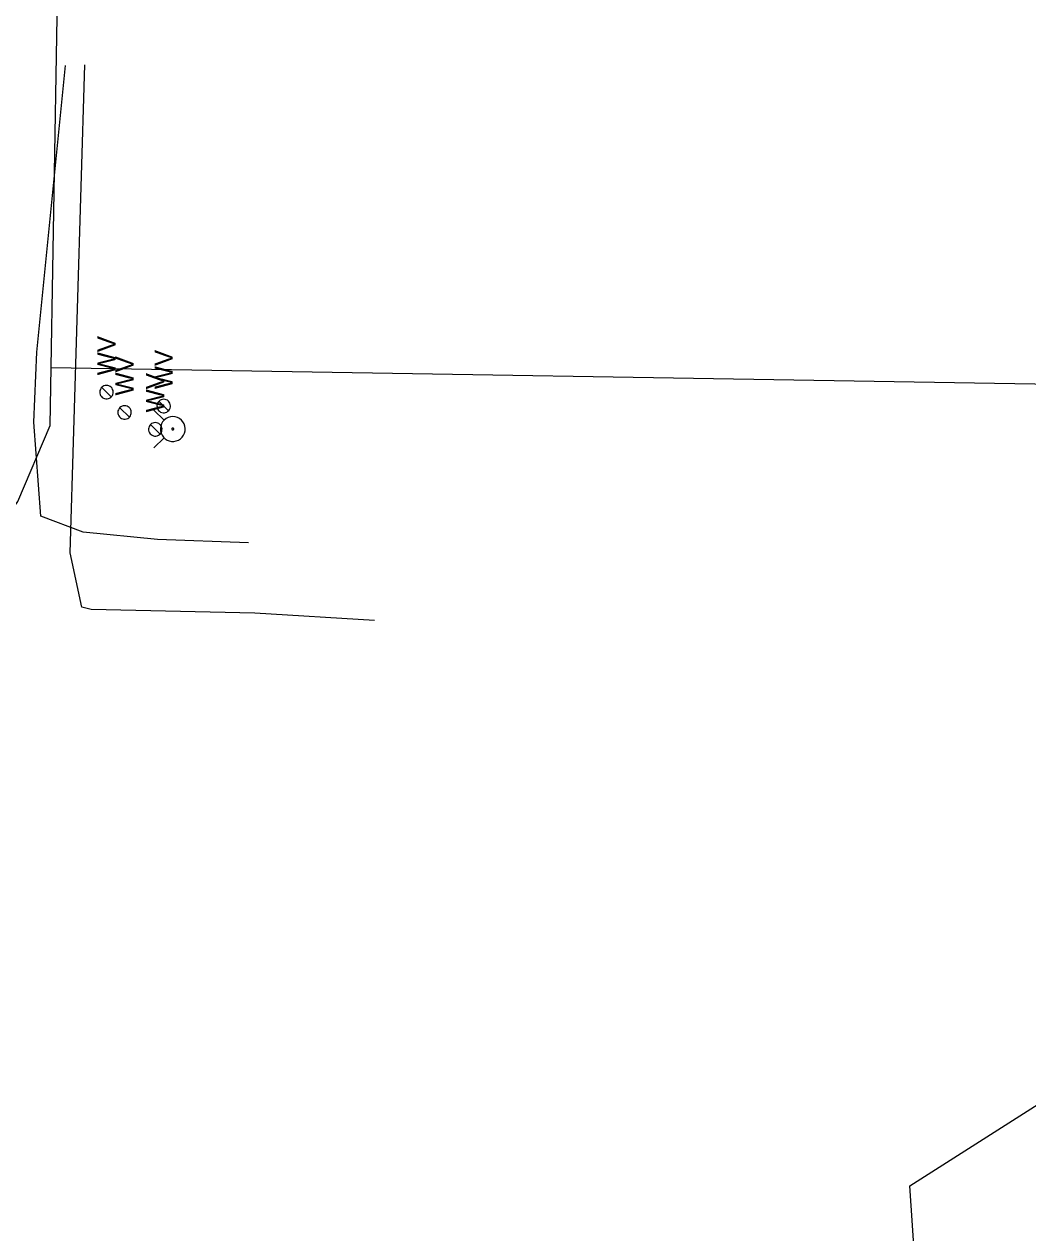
# Model space of a CAD drawing. Extents: x 596028 to 606371, y 330010 to 403088.
# Drawn here: x 604631.6 to 604843.1, y 338176.7 to 338431.5 of the extents above; entities that cross this region are included whole.
import ezdxf

# ---------------------------------------------------------------- set-up
doc = ezdxf.new("R2010")
doc.units = 0
for name, color, linetype in [('E_UTL_E_UG', 7, 'Continuous'), ('E_UTL_G_UG', 7, 'Continuous'), ('E_UTL_W', 7, 'Continuous'), ('E_UTL_WHydrant', 7, 'Continuous')]:
    doc.layers.add(name, color=color, linetype=linetype)

msp = doc.modelspace()

# ---------------------------------------------------------------- linework, layer by layer
at = {"layer": 'E_UTL_E_UG'}
for p, q in [((604637.05, 338346.84), (604638.82, 338452.87)), ((604637.25, 338359.09), (604911.55, 338354.56))]:
    msp.add_line(p, q, dxfattribs=at)
for points in [[(604678.85, 338322.09), (604659.64, 338322.8), (604643.99, 338324.36), (604635.04, 338327.77), (604633.62, 338347.59), (604634.2, 338362.29), (604640.26, 338422.74)], [(604617.83, 338316.39), (604626.08, 338325.01), (604630.22, 338330.84), (604637.05, 338346.84)], [(604825.46, 338093.49), (604823.34, 338111.37), (604818.25, 338186.57), (604849.14, 338206.21), (604870.72, 338198.67)]]:
    msp.add_lwpolyline(points, dxfattribs=at)
at = {"layer": 'E_UTL_G_UG'}
msp.add_lwpolyline([(604705.4, 338305.74), (604680.17, 338307.27), (604645.65, 338308.04), (604643.7, 338308.56), (604641.22, 338319.99), (604644.37, 338422.86)], dxfattribs=at)
at = {"layer": 'E_UTL_W'}
for points in [[(604648.9, 338355.3), (604648.63, 338355.28), (604648.37, 338355.2), (604648.13, 338355.08), (604647.92, 338354.91), (604647.74, 338354.7), (604647.61, 338354.47), (604647.52, 338354.21), (604647.48, 338353.95), (604647.49, 338353.67), (604647.56, 338353.41), (604647.67, 338353.16), (604647.83, 338352.94), (604648.02, 338352.76), (604648.25, 338352.61), (604648.5, 338352.51), (604648.77, 338352.46), (604649.04, 338352.46), (604649.31, 338352.51), (604649.56, 338352.61), (604649.79, 338352.76), (604649.98, 338352.94), (604650.14, 338353.16), (604650.25, 338353.41), (604650.31, 338353.67), (604650.33, 338353.95), (604650.29, 338354.21), (604650.2, 338354.47), (604650.07, 338354.7), (604649.89, 338354.91), (604649.67, 338355.08), (604649.43, 338355.2), (604649.17, 338355.28), (604648.9, 338355.3)], [(604649.91, 338352.87), (604647.9, 338354.89)], [(604652.72, 338351.03), (604652.45, 338351), (604652.19, 338350.93), (604651.95, 338350.8), (604651.74, 338350.63), (604651.56, 338350.43), (604651.42, 338350.19), (604651.33, 338349.94), (604651.3, 338349.67), (604651.31, 338349.4), (604651.37, 338349.14), (604651.49, 338348.89), (604651.64, 338348.67), (604651.84, 338348.48), (604652.07, 338348.33), (604652.32, 338348.23), (604652.59, 338348.18), (604652.86, 338348.18), (604653.12, 338348.23), (604653.37, 338348.33), (604653.6, 338348.48), (604653.8, 338348.67), (604653.96, 338348.89), (604654.07, 338349.14), (604654.13, 338349.4), (604654.14, 338349.67), (604654.11, 338349.94), (604654.02, 338350.19), (604653.88, 338350.43), (604653.7, 338350.63), (604653.49, 338350.8), (604653.25, 338350.93), (604652.99, 338351), (604652.72, 338351.03)], [(604653.73, 338348.59), (604651.71, 338350.61)], [(604660.97, 338352.38), (604660.7, 338352.36), (604660.44, 338352.28), (604660.2, 338352.16), (604659.98, 338351.99), (604659.81, 338351.79), (604659.67, 338351.55), (604659.58, 338351.29), (604659.54, 338351.03), (604659.56, 338350.76), (604659.62, 338350.49), (604659.73, 338350.25), (604659.89, 338350.02), (604660.09, 338349.84), (604660.31, 338349.69), (604660.57, 338349.59), (604660.83, 338349.54), (604661.1, 338349.54), (604661.37, 338349.59), (604661.62, 338349.69), (604661.85, 338349.84), (604662.05, 338350.02), (604662.2, 338350.25), (604662.32, 338350.49), (604662.38, 338350.76), (604662.39, 338351.03), (604662.35, 338351.29), (604662.26, 338351.55), (604662.13, 338351.79), (604661.95, 338351.99), (604661.74, 338352.16), (604661.5, 338352.28), (604661.24, 338352.36), (604660.97, 338352.38)], [(604661.98, 338349.95), (604659.96, 338351.97)], [(604659.19, 338347.48), (604658.92, 338347.45), (604658.66, 338347.38), (604658.42, 338347.25), (604658.2, 338347.09), (604658.03, 338346.88), (604657.89, 338346.65), (604657.8, 338346.39), (604657.76, 338346.12), (604657.78, 338345.85), (604657.84, 338345.59), (604657.95, 338345.34), (604658.11, 338345.12), (604658.31, 338344.93), (604658.53, 338344.79), (604658.79, 338344.69), (604659.05, 338344.63), (604659.32, 338344.63), (604659.59, 338344.69), (604659.84, 338344.79), (604660.07, 338344.93), (604660.27, 338345.12), (604660.42, 338345.34), (604660.54, 338345.59), (604660.6, 338345.85), (604660.61, 338346.12), (604660.57, 338346.39), (604660.48, 338346.65), (604660.35, 338346.88), (604660.17, 338347.09), (604659.96, 338347.25), (604659.72, 338347.38), (604659.46, 338347.45), (604659.19, 338347.48)], [(604660.2, 338345.05), (604658.18, 338347.06)]]:
    msp.add_lwpolyline(points, dxfattribs=at)
at = {"layer": 'E_UTL_WHydrant'}
for points in [[(604661.04, 338347.95), (604658.9, 338350.09)], [(604662.88, 338348.74), (604662.38, 338348.69), (604661.9, 338348.55), (604661.46, 338348.32), (604661.07, 338348.01), (604660.74, 338347.64), (604660.49, 338347.2), (604660.33, 338346.73), (604660.26, 338346.24), (604660.28, 338345.74), (604660.4, 338345.26), (604660.61, 338344.8), (604660.89, 338344.4), (604661.26, 338344.05), (604661.68, 338343.78), (604662.14, 338343.6), (604662.63, 338343.5), (604663.13, 338343.5), (604663.62, 338343.6), (604664.08, 338343.78), (604664.5, 338344.05), (604664.86, 338344.4), (604665.15, 338344.8), (604665.36, 338345.26), (604665.47, 338345.74), (604665.5, 338346.24), (604665.43, 338346.73), (604665.26, 338347.2), (604665.01, 338347.64), (604664.69, 338348.01), (604664.29, 338348.32), (604663.85, 338348.55), (604663.37, 338348.69), (604662.88, 338348.74)], [(604662.88, 338346.32), (604662.84, 338346.31), (604662.8, 338346.3), (604662.77, 338346.28), (604662.74, 338346.26), (604662.71, 338346.23), (604662.69, 338346.2), (604662.68, 338346.16), (604662.68, 338346.12), (604662.68, 338346.09), (604662.69, 338346.05), (604662.7, 338346.01), (604662.73, 338345.98), (604662.75, 338345.96), (604662.79, 338345.94), (604662.82, 338345.92), (604662.86, 338345.92), (604662.9, 338345.92), (604662.93, 338345.92), (604662.97, 338345.94), (604663, 338345.96), (604663.03, 338345.98), (604663.05, 338346.01), (604663.07, 338346.05), (604663.08, 338346.09), (604663.08, 338346.12), (604663.07, 338346.16), (604663.06, 338346.2), (604663.04, 338346.23), (604663.02, 338346.26), (604662.99, 338346.28), (604662.95, 338346.3), (604662.91, 338346.31), (604662.88, 338346.32)], [(604661.04, 338344.28), (604658.9, 338342.14)]]:
    msp.add_lwpolyline(points, dxfattribs=at)

# ---------------------------------------------------------------- texts
at = {"layer": 'E_UTL_W'}
for p in [(604650.83, 338357.44), (604654.65, 338353.17), (604662.89, 338354.52), (604661.11, 338349.62)]:
    msp.add_text('WV', height=3.85, rotation=90, dxfattribs=at).set_placement(p)

doc.saveas('drawing.dxf')
